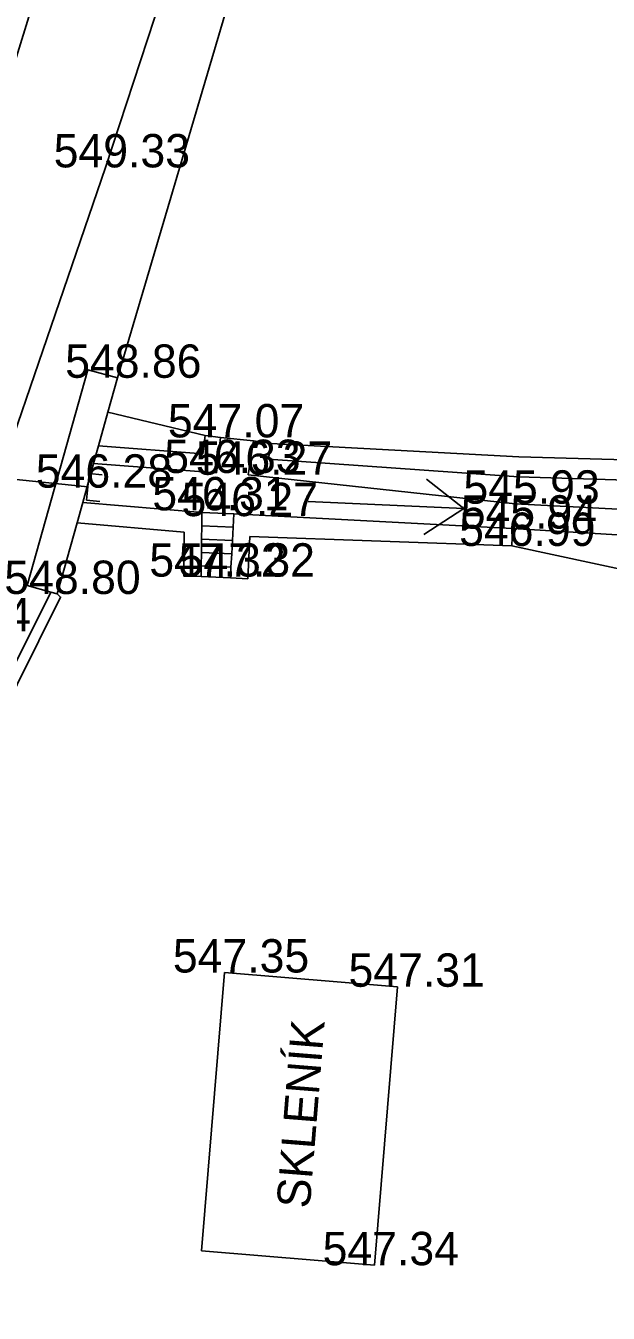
# Model space of a CAD drawing. Extents: x -669995 to -669686, y -1125551 to -1125263.
# Drawn here: x -669829.31 to -669816.2, y -1125387.03 to -1125358.09 of the extents above; entities that cross this region are included whole.
import ezdxf

# ---------------------------------------------------------------- set-up
doc = ezdxf.new("R2010")
doc.units = 0
for name, color, linetype in [('G_Bod_tecka', 7, 'Continuous'), ('G_Bod_vyska', 7, 'Continuous'), ('G_Breh_Teren', 7, 'Continuous'), ('G_Budovy_vstupy', 7, 'Continuous'), ('G_Cesty_Schody', 7, 'Continuous'), ('G_Plochy_zpevnene', 7, 'Continuous'), ('G_Ploty', 7, 'Continuous'), ('G_Popisy_Nazvy', 7, 'Continuous'), ('G_Poznamky_odkaz', 7, 'Continuous'), ('G_Site-kanalizace', 7, 'Continuous'), ('G_Z_KANAL_podz_kotovane', 7, 'Continuous'), ('Vrstva 21', 7, 'Continuous')]:
    doc.layers.add(name, color=color, linetype=linetype)

msp = doc.modelspace()

# ---------------------------------------------------------------- linework, layer by layer
at = {"layer": 'G_Bod_tecka'}
for p, q in [((-669827.51, -1125361.27), (-669827.51, -1125361.27)), ((-669827.24, -1125366), (-669827.24, -1125366)), ((-669824.92, -1125367.34), (-669824.92, -1125367.34)), ((-669825.01, -1125368.14), (-669825.01, -1125368.14)), ((-669824.3, -1125368.18), (-669824.3, -1125368.18)), ((-669827.9, -1125368.47), (-669827.9, -1125368.47)), ((-669818.29, -1125368.83), (-669818.29, -1125368.83)), ((-669825.34, -1125368.98), (-669825.34, -1125368.98)), ((-669824.62, -1125369.11), (-669824.62, -1125369.11)), ((-669818.35, -1125369.39), (-669818.35, -1125369.39)), ((-669818.37, -1125369.78), (-669818.37, -1125369.78)), ((-669825.36, -1125370.47), (-669825.36, -1125370.47)), ((-669824.7, -1125370.47), (-669824.7, -1125370.47)), ((-669828.6, -1125370.86), (-669828.6, -1125370.86)), ((-669824.83, -1125379.37), (-669824.83, -1125379.37)), ((-669820.94, -1125379.69), (-669820.94, -1125379.69)), ((-669821.46, -1125385.95), (-669821.46, -1125385.95))]:
    msp.add_line(p, q, dxfattribs=at)
at = {"layer": 'G_Breh_Teren'}
msp.add_line((-669818.37, -1125369.78), (-669807.66, -1125372.07), dxfattribs=at)
msp.add_lwpolyline([(-669818.35, -1125369.39), (-669807.42, -1125370.05), (-669788.12, -1125371.33), (-669766.46, -1125372.7), (-669749.86, -1125374)], dxfattribs=at)
at = {"layer": 'G_Budovy_vstupy'}
msp.add_line((-669824.92, -1125367.34), (-669824.18, -1125367.42), dxfattribs=at)
at = {"layer": 'G_Cesty_Schody'}
for p, q in [((-669825.34, -1125369.03), (-669824.62, -1125369.06)), ((-669825.34, -1125369.33), (-669824.64, -1125369.36)), ((-669825.35, -1125369.63), (-669824.65, -1125369.66)), ((-669825.35, -1125369.93), (-669824.67, -1125369.96)), ((-669825.36, -1125370.23), (-669824.69, -1125370.26)), ((-669825.36, -1125370.47), (-669824.7, -1125370.5)), ((-669824.83, -1125379.37), (-669825.35, -1125385.63)), ((-669824.83, -1125379.37), (-669820.94, -1125379.69)), ((-669820.94, -1125379.69), (-669821.46, -1125385.95)), ((-669825.35, -1125385.63), (-669821.46, -1125385.95))]:
    msp.add_line(p, q, dxfattribs=at)
at = {"layer": 'G_Plochy_zpevnene'}
for p, q in [((-669827.51, -1125361.27), (-669822.69, -1125346.56)), ((-669831.09, -1125371.7), (-669827.51, -1125361.27)), ((-669827.91, -1125365.82), (-669829.27, -1125370.67)), ((-669827.67, -1125367.53), (-669827.46, -1125366.77)), ((-669825.27, -1125367.3), (-669825.32, -1125367.71)), ((-669824.92, -1125367.34), (-669825.27, -1125367.3)), ((-669825.01, -1125368.14), (-669824.92, -1125367.34)), ((-669824.3, -1125368.18), (-669824.18, -1125367.42)), ((-669824.18, -1125367.42), (-669823.79, -1125367.48)), ((-669827.78, -1125367.93), (-669827.67, -1125367.53)), ((-669825.32, -1125367.71), (-669827.67, -1125367.53)), ((-669823.84, -1125367.83), (-669823.79, -1125367.48)), ((-669828.02, -1125368.8), (-669827.78, -1125367.93)), ((-669825.01, -1125368.14), (-669827.78, -1125367.93)), ((-669818.22, -1125368.23), (-669823.84, -1125367.83)), ((-669818.29, -1125368.83), (-669824.3, -1125368.18)), ((-669811.85, -1125368.42), (-669818.22, -1125368.23)), ((-669828.15, -1125369.26), (-669828.02, -1125368.8)), ((-669828.02, -1125368.8), (-669825.34, -1125369.03)), ((-669811.67, -1125369.18), (-669818.29, -1125368.83)), ((-669825.34, -1125369.03), (-669825.34, -1125369.33)), ((-669824.64, -1125369.36), (-669824.62, -1125369.06)), ((-669824.62, -1125369.06), (-669818.35, -1125369.39)), ((-669828.15, -1125369.26), (-669825.74, -1125369.47)), ((-669825.74, -1125369.47), (-669825.75, -1125370.46)), ((-669825.34, -1125369.33), (-669825.35, -1125369.63)), ((-669824.65, -1125369.66), (-669824.64, -1125369.36)), ((-669818.35, -1125369.39), (-669818.37, -1125369.78)), ((-669825.35, -1125369.63), (-669825.35, -1125369.93)), ((-669824.67, -1125369.96), (-669824.65, -1125369.66)), ((-669824.31, -1125370.52), (-669824.26, -1125369.57)), ((-669824.26, -1125369.57), (-669818.37, -1125369.78)), ((-669825.35, -1125369.93), (-669825.36, -1125370.23)), ((-669824.69, -1125370.26), (-669824.67, -1125369.96)), ((-669825.36, -1125370.23), (-669825.36, -1125370.47)), ((-669824.7, -1125370.5), (-669824.69, -1125370.26)), ((-669825.36, -1125370.47), (-669825.75, -1125370.46)), ((-669824.7, -1125370.5), (-669824.31, -1125370.52)), ((-669829.27, -1125370.67), (-669828.74, -1125370.82))]:
    msp.add_line(p, q, dxfattribs=at)
for points in [[(-669827.46, -1125366.77), (-669827.24, -1125366), (-669827.91, -1125365.82)], [(-669828.74, -1125370.82), (-669828.6, -1125370.86), (-669828.15, -1125369.26)]]:
    msp.add_lwpolyline(points, dxfattribs=at)
at = {"layer": 'G_Ploty'}
for p, q in [((-669827.24, -1125366), (-669819.44, -1125339.67)), ((-669825.27, -1125367.3), (-669827.46, -1125366.77)), ((-669818.21, -1125367.78), (-669823.79, -1125367.48)), ((-669811.76, -1125367.96), (-669818.21, -1125367.78)), ((-669831.2, -1125375.74), (-669828.74, -1125370.82))]:
    msp.add_line(p, q, dxfattribs=at)
msp.add_lwpolyline([(-669830.97, -1125375.84), (-669828.52, -1125370.93), (-669828.6, -1125370.86)], dxfattribs=at)
at = {"layer": 'G_Popisy_Nazvy'}
for p, q in [((-669820.29, -1125368.28), (-669819.45, -1125368.94)), ((-669822.947, -1125368.782), (-669819.45, -1125368.94)), ((-669819.45, -1125368.94), (-669820.347, -1125369.521))]:
    msp.add_line(p, q, dxfattribs=at)
at = {"layer": 'G_Site-kanalizace'}
for p, q in [((-669829.738, -1125368.267), (-669827.91, -1125368.45)), ((-669827.88, -1125368.151), (-669827.91, -1125368.45)), ((-669827.582, -1125368.181), (-669827.88, -1125368.151)), ((-669827.94, -1125368.749), (-669827.91, -1125368.45)), ((-669827.641, -1125368.778), (-669827.94, -1125368.749))]:
    msp.add_line(p, q, dxfattribs=at)
at = {"layer": 'G_Z_KANAL_podz_kotovane'}
msp.add_lwpolyline([(-669837.47, -1125406.42), (-669844.1, -1125405.26), (-669833.36, -1125371.21), (-669821.31, -1125332.23), (-669811.44, -1125307.86), (-669795.39, -1125283.71), (-669791, -1125278.72), (-669790.199, -1125277.833)], dxfattribs=at)
at = {"layer": 'Vrstva 21'}
msp.add_lwpolyline([(-669837.47, -1125406.42), (-669844.1, -1125405.26), (-669833.36, -1125371.21), (-669821.31, -1125332.23), (-669811.44, -1125307.86), (-669795.39, -1125283.71), (-669791, -1125278.72), (-669790.199, -1125277.833)], dxfattribs=at)

# ---------------------------------------------------------------- texts
at = {"layer": 'G_Bod_vyska'}
for s, p in [('549.33', (-669828.676, -1125361.27)), ('548.86', (-669828.418, -1125366)), ('547.07', (-669826.106, -1125367.34)), ('546.33', (-669826.188, -1125368.14)), ('546.27', (-669825.478, -1125368.18)), ('546.28', (-669829.078, -1125368.47)), ('546.31', (-669826.456, -1125368.98)), ('545.93', (-669819.456, -1125368.83)), ('546.27', (-669825.798, -1125369.11)), ('545.94', (-669819.516, -1125369.39)), ('546.99', (-669819.552, -1125369.78)), ('547.32', (-669826.524, -1125370.47)), ('547.32', (-669825.864, -1125370.47)), ('548.80', (-669829.786, -1125370.86)), ('549.34', (-669832.256, -1125371.7)), ('547.35', (-669825.994, -1125379.37)), ('547.31', (-669822.042, -1125379.69)), ('547.34', (-669822.624, -1125385.95))]:
    msp.add_text(s, height=0.75, dxfattribs=at).set_placement(p)
at = {"layer": 'G_Poznamky_odkaz'}
msp.add_text('SKLENÍK', height=0.75, rotation=85.4154, dxfattribs=at).set_placement((-669822.915, -1125384.688))

doc.saveas('drawing.dxf')
